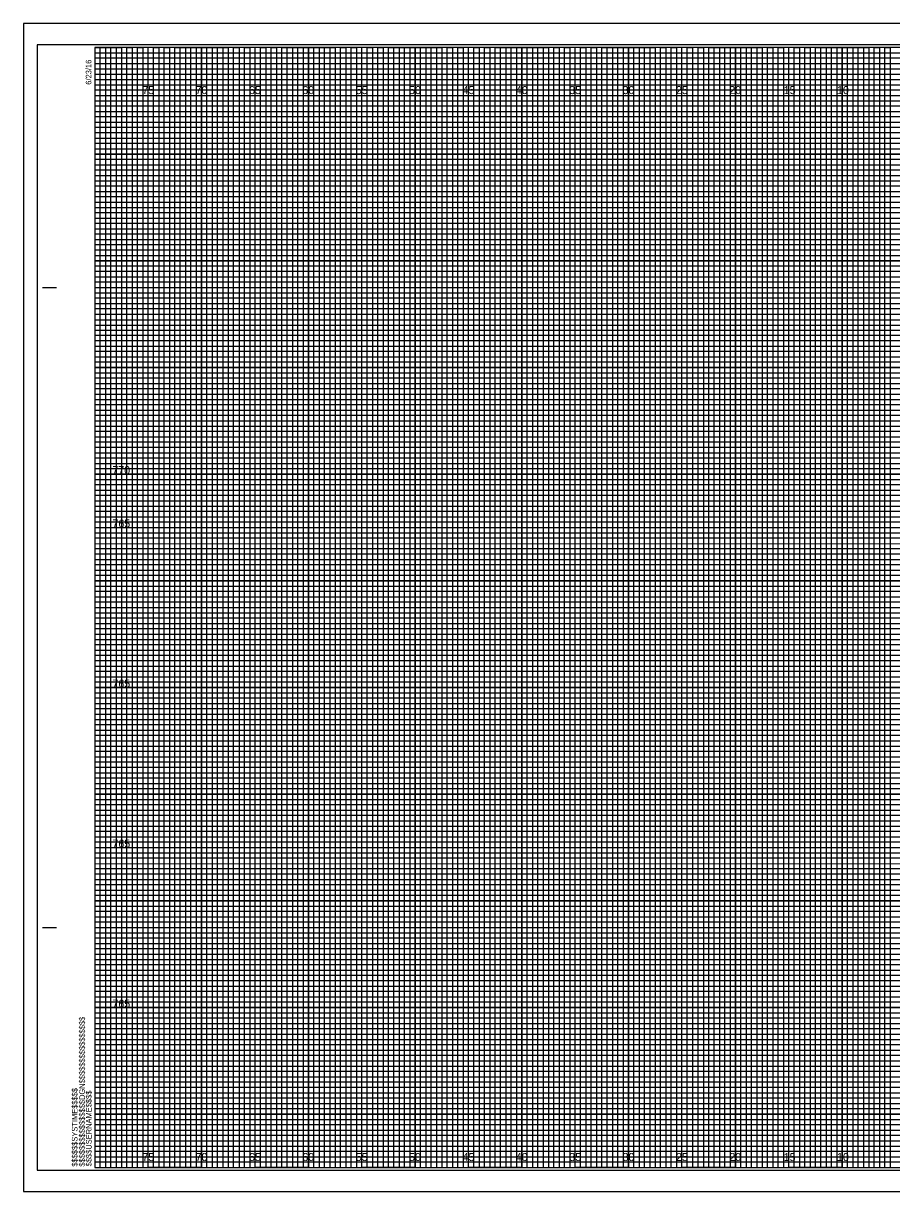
# Model space of a CAD drawing. Extents: x -7 to 162, y -2 to 107.
# Drawn here: x -6.7 to 74.6, y -2.3 to 107.3 of the extents above; entities that cross this region are included whole.
import ezdxf

# ---------------------------------------------------------------- set-up
doc = ezdxf.new("R2010")
doc.units = 0
for name, color, linetype in [('Exist XS Center Line Elevation Label', 7, 'Continuous'), ('Prop CMT Pvmt Course 1', 7, 'Continuous'), ('Prop CMT Pvmt Course 2', 7, 'Continuous'), ('Prop CMT Pvmt Course 3', 7, 'Continuous'), ('Prop CMT Pvmt Surface', 7, 'Continuous'), ('Prop CMT Shld Paved Course 1', 7, 'Continuous'), ('Prop CMT Shld Paved Course 2', 7, 'Continuous'), ('Prop CMT Shld Paved Course 3', 7, 'Continuous'), ('Prop CMT Subgrade Earthwork', 7, 'Continuous'), ('Prop XS SE Text', 7, 'Continuous'), ('Scratch_Level_5', 7, 'Continuous')]:
    doc.layers.add(name, color=color, linetype=linetype)

msp = doc.modelspace()

# ---------------------------------------------------------------- linework, layer by layer
at = {"layer": 'Prop CMT Pvmt Course 1'}
msp.add_lwpolyline([(-6.7, -2.25), (161.65, -2.25), (161.65, 107.25), (-6.7, 107.25)], close=True, dxfattribs=at)
at = {"layer": 'Prop CMT Pvmt Course 2'}
msp.add_lwpolyline([(-5.4, -0.25), (161.2, -0.25), (161.2, 105.25), (-5.4, 105.25)], close=True, dxfattribs=at)
at = {"layer": 'Prop CMT Pvmt Course 3'}
for p, q in [((5, 0), (5, 105)), ((10, 0), (10, 105)), ((15, 0), (15, 105)), ((20, 0), (20, 105)), ((25, 0), (25, 105)), ((30, 0), (30, 105)), ((35, 0), (35, 105)), ((40, 0), (40, 105)), ((45, 0), (45, 105)), ((50, 0), (50, 105)), ((55, 0), (55, 105)), ((60, 0), (60, 105)), ((65, 0), (65, 105)), ((70, 0), (70, 105)), ((0, 100), (160, 100)), ((0, 95), (160, 95)), ((0, 90), (160, 90)), ((0, 85), (160, 85)), ((0, 80), (160, 80)), ((0, 75), (160, 75)), ((0, 70), (160, 70)), ((0, 65), (160, 65)), ((0, 60), (160, 60)), ((0, 55), (160, 55)), ((0, 50), (160, 50)), ((0, 45), (160, 45)), ((0, 40), (160, 40)), ((0, 35), (160, 35)), ((0, 30), (160, 30)), ((0, 25), (160, 25)), ((0, 20), (160, 20)), ((0, 15), (160, 15)), ((0, 10), (160, 10)), ((0, 5), (160, 5))]:
    msp.add_line(p, q, dxfattribs=at)
at = {"layer": 'Prop CMT Pvmt Surface'}
for points in [[(0, 0), (0.5, 0), (0.5, 105), (1, 105), (1, 0)], [(1, 0), (1.5, 0), (1.5, 105), (2, 105), (2, 0)], [(2.5, 0), (3, 0), (3, 105), (3.5, 105), (3.5, 0)], [(3.5, 0), (4, 0), (4, 105), (4.5, 105), (4.5, 0)], [(5, 0), (5.5, 0), (5.5, 105), (6, 105), (6, 0)], [(6, 0), (6.5, 0), (6.5, 105), (7, 105), (7, 0)], [(7.5, 0), (8, 0), (8, 105), (8.5, 105), (8.5, 0)], [(8.5, 0), (9, 0), (9, 105), (9.5, 105), (9.5, 0)], [(10, 0), (10.5, 0), (10.5, 105), (11, 105), (11, 0)], [(11, 0), (11.5, 0), (11.5, 105), (12, 105), (12, 0)], [(12.5, 0), (13, 0), (13, 105), (13.5, 105), (13.5, 0)], [(13.5, 0), (14, 0), (14, 105), (14.5, 105), (14.5, 0)], [(15, 0), (15.5, 0), (15.5, 105), (16, 105), (16, 0)], [(16, 0), (16.5, 0), (16.5, 105), (17, 105), (17, 0)], [(17.5, 0), (18, 0), (18, 105), (18.5, 105), (18.5, 0)], [(18.5, 0), (19, 0), (19, 105), (19.5, 105), (19.5, 0)], [(20, 0), (20.5, 0), (20.5, 105), (21, 105), (21, 0)], [(21, 0), (21.5, 0), (21.5, 105), (22, 105), (22, 0)], [(22.5, 0), (23, 0), (23, 105), (23.5, 105), (23.5, 0)], [(23.5, 0), (24, 0), (24, 105), (24.5, 105), (24.5, 0)], [(25, 0), (25.5, 0), (25.5, 105), (26, 105), (26, 0)], [(26, 0), (26.5, 0), (26.5, 105), (27, 105), (27, 0)], [(27.5, 0), (28, 0), (28, 105), (28.5, 105), (28.5, 0)], [(28.5, 0), (29, 0), (29, 105), (29.5, 105), (29.5, 0)], [(30, 0), (30.5, 0), (30.5, 105), (31, 105), (31, 0)], [(31, 0), (31.5, 0), (31.5, 105), (32, 105), (32, 0)], [(32.5, 0), (33, 0), (33, 105), (33.5, 105), (33.5, 0)], [(33.5, 0), (34, 0), (34, 105), (34.5, 105), (34.5, 0)], [(35, 0), (35.5, 0), (35.5, 105), (36, 105), (36, 0)], [(36, 0), (36.5, 0), (36.5, 105), (37, 105), (37, 0)], [(37.5, 0), (38, 0), (38, 105), (38.5, 105), (38.5, 0)], [(38.5, 0), (39, 0), (39, 105), (39.5, 105), (39.5, 0)], [(40, 0), (40.5, 0), (40.5, 105), (41, 105), (41, 0)], [(41, 0), (41.5, 0), (41.5, 105), (42, 105), (42, 0)], [(42.5, 0), (43, 0), (43, 105), (43.5, 105), (43.5, 0)], [(43.5, 0), (44, 0), (44, 105), (44.5, 105), (44.5, 0)], [(45, 0), (45.5, 0), (45.5, 105), (46, 105), (46, 0)], [(46, 0), (46.5, 0), (46.5, 105), (47, 105), (47, 0)], [(47.5, 0), (48, 0), (48, 105), (48.5, 105), (48.5, 0)], [(48.5, 0), (49, 0), (49, 105), (49.5, 105), (49.5, 0)], [(50, 0), (50.5, 0), (50.5, 105), (51, 105), (51, 0)], [(51, 0), (51.5, 0), (51.5, 105), (52, 105), (52, 0)], [(52.5, 0), (53, 0), (53, 105), (53.5, 105), (53.5, 0)], [(53.5, 0), (54, 0), (54, 105), (54.5, 105), (54.5, 0)], [(55, 0), (55.5, 0), (55.5, 105), (56, 105), (56, 0)], [(56, 0), (56.5, 0), (56.5, 105), (57, 105), (57, 0)], [(57.5, 0), (58, 0), (58, 105), (58.5, 105), (58.5, 0)], [(58.5, 0), (59, 0), (59, 105), (59.5, 105), (59.5, 0)], [(60, 0), (60.5, 0), (60.5, 105), (61, 105), (61, 0)], [(61, 0), (61.5, 0), (61.5, 105), (62, 105), (62, 0)], [(62.5, 0), (63, 0), (63, 105), (63.5, 105), (63.5, 0)], [(63.5, 0), (64, 0), (64, 105), (64.5, 105), (64.5, 0)], [(65, 0), (65.5, 0), (65.5, 105), (66, 105), (66, 0)], [(66, 0), (66.5, 0), (66.5, 105), (67, 105), (67, 0)], [(67.5, 0), (68, 0), (68, 105), (68.5, 105), (68.5, 0)], [(68.5, 0), (69, 0), (69, 105), (69.5, 105), (69.5, 0)], [(70, 0), (70.5, 0), (70.5, 105), (71, 105), (71, 0)], [(71, 0), (71.5, 0), (71.5, 105), (72, 105), (72, 0)], [(72.5, 0), (73, 0), (73, 105), (73.5, 105), (73.5, 0)], [(73.5, 0), (74, 0), (74, 105), (74.5, 105), (74.5, 0)]]:
    msp.add_lwpolyline(points, dxfattribs=at)
at = {"layer": 'Prop CMT Shld Paved Course 1'}
for p, q in [((5, 105), (0, 105)), ((5, 0), (5, 105)), ((15, 105), (10, 105)), ((10, 105), (10, 0)), ((15, 0), (15, 105)), ((25, 105), (20, 105)), ((20, 105), (20, 0)), ((25, 0), (25, 105)), ((35, 105), (30, 105)), ((30, 105), (30, 0)), ((35, 0), (35, 105)), ((45, 105), (40, 105)), ((40, 105), (40, 0)), ((45, 0), (45, 105)), ((55, 105), (50, 105)), ((50, 105), (50, 0)), ((55, 0), (55, 105)), ((65, 105), (60, 105)), ((60, 105), (60, 0)), ((65, 0), (65, 105)), ((75, 105), (70, 105)), ((70, 105), (70, 0)), ((10, 0), (5, 0)), ((20, 0), (15, 0)), ((30, 0), (25, 0)), ((40, 0), (35, 0)), ((50, 0), (45, 0)), ((60, 0), (55, 0)), ((70, 0), (65, 0))]:
    msp.add_line(p, q, dxfattribs=at)
for points in [[(0, 100), (160, 100), (160, 95), (0, 95)], [(0, 90), (160, 90), (160, 85), (0, 85)], [(0, 80), (160, 80), (160, 75), (0, 75)], [(0, 70), (160, 70), (160, 65), (0, 65)], [(0, 60), (160, 60), (160, 55), (0, 55)], [(0, 50), (160, 50), (160, 45), (0, 45)], [(0, 40), (160, 40), (160, 35), (0, 35)], [(0, 30), (160, 30), (160, 25), (0, 25)], [(0, 20), (160, 20), (160, 15), (0, 15)], [(0, 10), (160, 10), (160, 5), (0, 5)]]:
    msp.add_lwpolyline(points, dxfattribs=at)
at = {"layer": 'Prop CMT Shld Paved Course 2'}
for points in [[(0, 105), (2.5, 105), (2.5, 0), (7.5, 0), (7.5, 105), (12.5, 105), (12.5, 0), (17.5, 0), (17.5, 105), (22.5, 105), (22.5, 0), (27.5, 0), (27.5, 105), (32.5, 105), (32.5, 0), (37.5, 0), (37.5, 105), (42.5, 105), (42.5, 0), (47.5, 0), (47.5, 105), (52.5, 105), (52.5, 0), (57.5, 0), (57.5, 105), (62.5, 105), (62.5, 0), (67.5, 0), (67.5, 105), (72.5, 105), (72.5, 0), (77.5, 0)], [(0, 102.5), (137.5, 102.5)], [(0, 92.5), (160, 92.5), (160, 97.5), (0, 97.5)], [(0, 82.5), (160, 82.5), (160, 87.5), (0, 87.5)], [(0, 72.5), (160, 72.5), (160, 77.5), (0, 77.5)], [(0, 62.5), (160, 62.5), (160, 67.5), (0, 67.5)], [(0, 52.5), (160, 52.5), (160, 57.5), (0, 57.5)], [(0, 42.5), (160, 42.5), (160, 47.5), (0, 47.5)], [(0, 32.5), (160, 32.5), (160, 37.5), (0, 37.5)], [(0, 22.5), (160, 22.5), (160, 27.5), (0, 27.5)], [(0, 12.5), (160, 12.5), (160, 17.5), (0, 17.5)], [(0, 2.5), (160, 2.5), (160, 7.5), (0, 7.5)]]:
    msp.add_lwpolyline(points, dxfattribs=at)
at = {"layer": 'Prop CMT Shld Paved Course 3'}
for p, q in [((0, 104.5), (130, 104.5)), ((130, 103.99), (0, 103.99)), ((0, 103.99), (0, 103.5)), ((0, 103.5), (130, 103.5)), ((130, 102.95), (0, 102.95)), ((0, 102.95), (0, 102)), ((0, 102), (160, 102))]:
    msp.add_line(p, q, dxfattribs=at)
for points in [[(0, 101.5), (135, 101.5), (160, 101.5), (160, 101), (0, 101)], [(0, 100.5), (160, 100.5), (160, 99.5), (0, 99.5)], [(0, 99), (160, 99), (160, 98.5), (0, 98.49)], [(0, 98), (160, 98), (160, 97), (0, 97)], [(0, 96.5), (160, 96.5), (160, 96), (0, 96)], [(0, 95.5), (160, 95.5), (160, 94.5), (0, 94.5)], [(0, 94), (160, 94), (160, 93.5), (0, 93.5)], [(0, 93), (160, 93), (160, 92), (0, 92)], [(0, 91.5), (160, 91.5), (160, 91), (0, 91)], [(0, 90.5), (160, 90.5), (160, 89.5), (0, 89.5)], [(0, 89), (160, 89), (160, 88.5), (0, 88.5)], [(0, 88), (160, 88), (160, 86.98), (160, 86.5), (160, 86), (0, 86)], [(0, 87), (160, 87), (160, 86.5), (0, 86.5)], [(0, 85.5), (160, 85.5), (160, 84.5), (0, 84.52)], [(0, 84.52), (160, 84.5), (160, 84), (0, 84)], [(0, 83.5), (160, 83.5), (160, 83), (0, 83)], [(0, 82), (160, 82), (160, 81.5), (0, 81.5)], [(0, 81), (160, 81), (160, 80.5), (0, 80.5)], [(-0.04, 79.45), (160, 79.45), (160, 78.94), (-0.04, 78.94)], [(0, 78.5), (160, 78.5), (160, 78), (0, 78)], [(0, 77), (160, 77), (160, 76.5), (0, 76.5)], [(0, 76), (160, 76), (160, 75.5), (0, 75.5)], [(0, 74.5), (160, 74.5), (160, 74), (0, 74)], [(0, 73.5), (160, 73.5), (160, 73), (0, 73)], [(0, 72), (160, 72), (160, 71.5), (0, 71.5)], [(0, 71), (160, 71), (160, 70.5), (0, 70.5)], [(0, 69.5), (160, 69.5), (160, 68.99), (0, 69)], [(0, 68.5), (160, 68.5), (160, 68), (0, 68)], [(0, 67), (160, 67), (160, 66.5), (0, 66.5)], [(0, 66), (160, 66), (160, 65.5), (0, 65.5)], [(0, 64.5), (160, 64.5), (160, 64), (0, 64)], [(0, 63.5), (160, 63.5), (160, 63), (0, 63)], [(0, 62), (160, 62), (160, 61.5), (0, 61.5)], [(0, 61), (160, 61), (160, 60.5), (0, 60.5)], [(0, 59.5), (160, 59.5), (160, 59), (0, 59)], [(0, 58.5), (160.03, 58.45), (160, 58), (0, 58)], [(0, 57), (160, 57), (160, 56.5), (0, 56.5)], [(0, 56), (160, 56), (160, 55.5), (0, 55.5)], [(0, 54.5), (160, 54.5), (160, 54), (0, 54)], [(0, 53.5), (160, 53.5), (160, 53), (0, 53)], [(0, 52), (160, 52), (160, 51.5), (0, 51.5)], [(0, 51), (160, 51), (160, 50.5), (0, 50.5)], [(0, 49.5), (160, 49.5), (160, 49), (0, 49)], [(0, 48.5), (160, 48.5), (160, 48), (0, 48)], [(0, 47), (160, 47), (160, 46.5), (0, 46.5)], [(0, 46), (160, 46), (160, 45.5), (0, 45.5)], [(0, 44.5), (160, 44.5), (160, 44), (0, 44)], [(0, 43.5), (160, 43.5), (160, 43), (0, 43)], [(0, 42), (160, 42), (160, 41.5), (0, 41.5)], [(0, 41), (160, 41), (160, 40.5), (0, 40.5)], [(0, 39.5), (160, 39.5), (160, 38.99), (0, 39)], [(0, 38.5), (160, 38.5), (160, 38), (0, 38)], [(0, 37), (160, 37), (160, 36.5), (0, 36.5)], [(0, 36), (160, 36), (160, 35.5), (0, 35.5)], [(0, 34.5), (160, 34.5), (160, 34), (0, 34)], [(0, 33.5), (160, 33.5), (160, 33), (0, 33)], [(0, 32), (160, 32), (160, 31.5), (0, 31.5)], [(0, 31), (160, 31), (160, 30.5), (0, 30.5)], [(0, 29.5), (160, 29.5), (160, 29), (0, 29)], [(0, 28.5), (160.03, 28.46), (160, 28), (0, 28)], [(0, 27), (160, 27), (160, 26.5), (0, 26.5)], [(0, 26), (160, 26), (160, 25.5), (0, 25.5)], [(0, 24.5), (160, 24.5), (160, 24), (0, 24)], [(0, 23.5), (160, 23.5), (160, 23), (0, 23)], [(0, 22), (160, 22), (160, 21.5), (0, 21.5)], [(0, 21), (160, 21), (160, 20.5), (0, 20.5)], [(0, 19.5), (160, 19.5), (160, 19), (0, 19)], [(0, 18.5), (160, 18.5), (160, 18), (0, 18)], [(0, 17), (160, 17), (160, 16.5), (0, 16.5)], [(0, 16), (160, 16), (160, 15.5), (0, 15.5)], [(0, 14.5), (160, 14.5), (160, 14), (0, 14)], [(0, 13.5), (160, 13.5), (160, 13), (0, 13)], [(0, 12), (160, 12), (160, 11.5), (0, 11.5)], [(0, 11), (160, 11), (160, 10.5), (0, 10.5)], [(0, 9.5), (160, 9.5), (160, 9), (0, 9)], [(0, 8.5), (160, 8.5), (160, 8), (0, 8)], [(0, 7), (160, 7), (160, 6.5), (0, 6.5)], [(0, 6), (160, 6), (160, 5.5), (0, 5.5)], [(0, 4.5), (160, 4.5), (160, 4), (0, 4)], [(0, 3.5), (160, 3.5), (160, 3), (0, 3)], [(0, 2), (160, 2), (160, 1.5), (0, 1.5)], [(0, 1), (160, 1), (160, 0.5), (0, 0.5)]]:
    msp.add_lwpolyline(points, dxfattribs=at)
at = {"layer": 'Prop CMT Subgrade Earthwork'}
for p, q in [((-4.9, 82.5), (-3.65, 82.5)), ((-4.85, 82.5), (-3.6, 82.5)), ((-4.9, 22.5), (-3.65, 22.5)), ((-4.85, 22.5), (-3.6, 22.5)), ((0, 0), (0, 0)), ((0, 0), (0, 0)), ((0, 0), (0, 0)), ((0, 0), (0, 0)), ((0, 0), (0, 0)), ((0, 0), (0, 0)), ((0, 0), (0, 0))]:
    msp.add_line(p, q, dxfattribs=at)
msp.add_lwpolyline([(160, 105), (0, 105), (0, 0), (160, 0)], close=True, dxfattribs=at)
at = {"layer": 'Prop XS SE Text'}
for p, q in [((161.65, 107.25), (-6.7, 107.25)), ((-6.7, 107.25), (-6.7, -2.25)), ((-6.7, -2.25), (161.65, -2.25))]:
    msp.add_line(p, q, dxfattribs=at)

# ---------------------------------------------------------------- texts
at = {"layer": 'Exist XS Center Line Elevation Label'}
for s, p in [('75', (4.44, 100.62)), ('70', (9.43, 100.62)), ('65', (14.44, 100.62)), ('60', (19.43, 100.62)), ('55', (24.44, 100.62)), ('50', (29.43, 100.62)), ('45', (34.44, 100.62)), ('40', (39.43, 100.62)), ('35', (44.44, 100.62)), ('30', (49.43, 100.62)), ('25', (54.44, 100.62)), ('20', (59.43, 100.62)), ('15', (64.53, 100.62)), ('10', (69.52, 100.62)), ('75', (4.44, 0.62)), ('70', (9.43, 0.62)), ('65', (14.44, 0.62)), ('60', (19.43, 0.62)), ('55', (24.44, 0.62)), ('50', (29.43, 0.62)), ('45', (34.44, 0.62)), ('40', (39.43, 0.62)), ('35', (44.44, 0.62)), ('30', (49.43, 0.62)), ('25', (54.44, 0.62)), ('20', (59.43, 0.62)), ('15', (64.53, 0.62)), ('10', (69.52, 0.62))]:
    msp.add_text(s, height=0.75, dxfattribs=at).set_placement(p)
at = {"layer": 'Prop CMT Subgrade Earthwork'}
for s, p in [('6/23/16', (-0.33, 101.5)), ('$$$$$$$$$$$$$$$$DGN$$$$$$$$$$$$$$$$', (-0.94, 0.09)), ('$$$$$$SYSTIME$$$$$', (-1.63, 0.09)), ('$$$$USERNAME$$$$', (-0.31, 0.12))]:
    msp.add_text(s, height=0.525, rotation=90, dxfattribs=at).set_placement(p)
at = {"layer": 'Scratch_Level_5'}
for s, p in [('770', (1.63, 65)), ('765', (1.64, 60)), ('765', (1.64, 45)), ('765', (1.64, 30)), ('765', (1.64, 15))]:
    msp.add_text(s, height=0.75, dxfattribs=at).set_placement(p)

doc.saveas('drawing.dxf')
